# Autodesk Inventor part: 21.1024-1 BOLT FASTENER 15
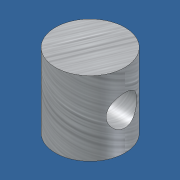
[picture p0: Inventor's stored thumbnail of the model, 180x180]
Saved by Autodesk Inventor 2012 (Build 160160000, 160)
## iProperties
Created: 2006-12
Part Number: 21.1024-1 BOLT FASTENER 15
Document SubType Name: Modeling
Designer: Andy Moles
Material: Aluminum-6061
Mass: 5.32319 g
Surface Area: 13.8401 cm^2
Volume: 1.96428 cm^3
Density: 2.71 g/cm^3
Author: Andy Moles
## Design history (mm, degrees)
sketch "Sketch1"
  geometry: C1 r 7.5 at (0, 0); 1 further point
  constraints: 1 centre point, 1 coincident
  dimensions: "d0" = 15 diameter of C1
extrude "Extrusion1" new body sketch "Sketch1" distance "d1" = 16; taper "d2" = 0 deg
workplane "Work Plane1"
sketch "Sketch2"
  geometry: L1 (7.5, 0)-(7.5, 16) reference; L2 (-7.5, 16)-(7.5, 16) reference; L3 (-7.5, 0)-(7.5, 0) reference; L4 (7.5, 16)-(-7.5, 0); C1 r 5.5 at (0, 8); 1 further point
  constraints: 2 end point, 1 centre point, 1 midpoint
  dimensions: "d3" = 11 diameter of C1
extrude "Extrusion2" cut sketch "Sketch2" distance "d4" = 6.7; taper "d5" = 0 deg
sketch "Sketch3"
  geometry: C1 r 5.5 at (0, 0) reference; C2 r 3.3 at (0, 0); 1 further point
  constraints: 1 centre point, 1 coincident
  dimensions: "d6" = 6.6 diameter of C2
extrude "Extrusion3" cut sketch "Sketch3" stored distance "d7" = 6.7; taper "d8" = 0 deg
body "Solid1"
node "Projected Loop1"
